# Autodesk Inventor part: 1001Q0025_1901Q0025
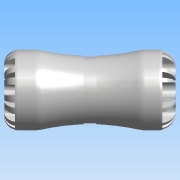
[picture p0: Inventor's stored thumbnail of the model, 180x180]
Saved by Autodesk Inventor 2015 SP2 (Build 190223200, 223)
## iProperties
Created: 2016-12
Part Number: 1001Q0025_1901Q0025
Material: PVC-Piping
Description: PLASSON PVC TO PE COUPLER 25 SERIES 1
Document SubType Name: Modeling
Designer: KIM
Mass: 95.2094 g
Surface Area: 200.83 cm^2
Volume: 68.0067 cm^3
Density: 1.4 g/cm^3
Appearance: Smooth - White
ILogicFactory: False
Author: KIM
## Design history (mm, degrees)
derived "1001Q.ipt"
feature "Solid1::1001Q.ipt"
tag "TaggingFeature1"
body "Solid1"
other parameters: "d1" = 47, "d2" = 48, "d11" = 6.3, "d13" = 6.3, "d14" = 0, "d16" = 360 deg, "d18" = 8 deg, "d19" = 0.5, "d20" = 8 deg, "d21" = 0.5, "d23" = 0, "d25" = 360 deg, "d27" = 18.8, "d28" = 7.5, "d29" = 7.5, "d30" = 12.348, "d31" = 0, "d33" = 0, "d38" = 0.47, "d44" = 25, "d47" = 47, "d50" = 360 deg, "d54" = 0.513, "d60" = 25, "d61" = 27.5, "d66" = 2.08333, "d70" = 8.775, "d72" = 7.8, "d73" = 0, "d75" = 360 deg, "d77" = 8 deg, "d78" = 8 deg, "d79" = 0.5, "d80" = 0.5, "d82" = 0, "d84" = 360 deg, "d87" = 31.25, "d93" = 47, "d94" = 39.95, "d_" = 25, "E_" = 47, "l_" = 48, "d_1" = 25, "d12" = 31.25, "d42" = 47, "d52" = 7.875, "d68" = 47, "d69" = 27.5, "d71" = 9.75
